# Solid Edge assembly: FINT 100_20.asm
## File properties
Title: Zylinder
Author: bmolnar
Template: iso assembly.asm
Last saved by: bmolnar
Revision: 12
Application: Solid Edge
Username: bmolnar
Dokumentum tartalom típus: 1
Document Number: FINT 100/20
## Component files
Kolbenstange.par
Profilrohr.par
Kit_1.par
Kit_2.par
Platte.par
hrungsstange.par
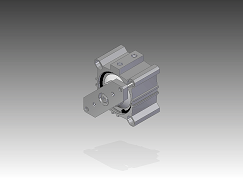
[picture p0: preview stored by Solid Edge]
